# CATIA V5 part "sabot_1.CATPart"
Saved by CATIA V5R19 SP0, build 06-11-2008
Part number: skl_sabot_1
Publications: "axe_pivot_sabot1_batit", "axe_pivot_sabot1_roue1", "axe_pivot_sabot1_bielette3", "Plan.1", "Point.2"
Bounding box of the stored display mesh (mm): x 110 to 240, y 330 to 560, z -20 to 20
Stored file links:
  C:\Users\Thibaud\Desktop\IFMA\thinkmotion\IAO\modele_catia\squelette\sabot_1.CATPart
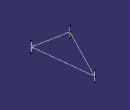
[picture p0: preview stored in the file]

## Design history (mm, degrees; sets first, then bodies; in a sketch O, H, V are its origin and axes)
Body1 (main body)
  Point1: stored without definition
  Point2: stored without definition
  Line1: type PtPt, SecondPoint Point2, FirstPoint Point1
  Point3: stored without definition
  Point4: stored without definition
  Line2: type PtPt, SecondPoint Point4, FirstPoint Point3
  Point5: stored without definition
  Point6: stored without definition
  Line3: type PtPt, SecondPoint Point6, FirstPoint Point5
  Plane1: stored without definition
  Point7: stored without definition
  Line4 "axe_pivot_sabot1_bielette3": type Normal, RefSkin Plane1, Start -20, End 20, RefPoint Point7
  Plane2: stored without definition
  Point8: stored without definition
  Line5 "axe_pivot_sabot1_roue1": type Normal, RefSkin Plane2, Start -20, End 20, RefPoint Point8
  Plane3: stored without definition
  Point9: stored without definition
  Line6 "axe_pivot_sabot1_batit": type Normal, RefSkin Plane3, Start -20, End 20, RefPoint Point9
